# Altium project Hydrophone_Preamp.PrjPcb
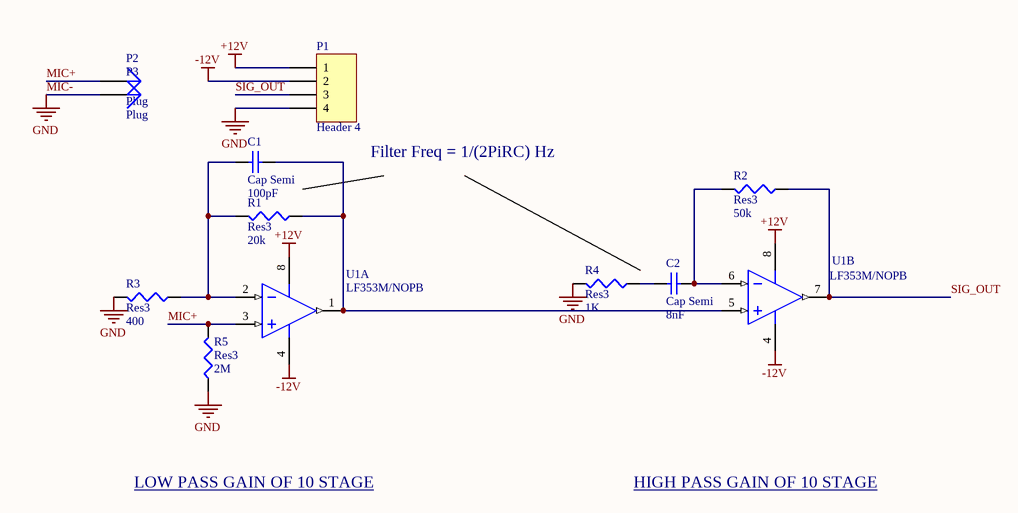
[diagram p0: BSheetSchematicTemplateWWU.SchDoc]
DraftsmanName: [GlobalDraftsmanName]; EngineerName: [GlobalEngineerName]; GlobalDate: [GlobalDate]; GlobalTitle: [GlobalTitle]; RevNumber: [GlobalRevNumber]
1 sheet, 12 parts. Net scope: flat (ports and power ports of the same name join across sheets).
Board file: 2LayerPCBTemplateWWU.PcbDoc

## Sheet BSheetSchematicTemplateWWU.SchDoc: [SheetTitle]
size B; Date: [Date]

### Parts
(Parts that share a designator on the sheet are numbered #1, #2 ... from top to bottom, then left to right.)
C1  Cap Semi  value 100pF  [1608[0603]]
C2  Cap Semi  value 8nF  [1608[0603]]
P1  Header 4  [HDR1X4]
P2  Plug  [PIN1]
P3  Plug  [PIN1]
R1  Res3  value 20k  [J1-0603]
R2  Res3  value 50k  [J1-0603]
R3  Res3  value 400  [J1-0603]
R4  Res3  value 1K  [J1-0603]
R5  Res3  value 2M  [J1-0603]
U1#1  LF353M/NOPB  [D0008A_L]  (part B of 2)
U1#2  LF353M/NOPB  [D0008A_M]  (part A of 2)

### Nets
+12V: P1.1 U1#1.8(V+) U1#2.8(V+)
-12V: P1.2 U1#1.4(V-) U1#2.4(V-)
MIC-: P1.4 P3.1 R3.2 R4.2 R5.1  [also labelled GND]
MIC+: P2.1 R5.2 U1#2.3(INA+)
SIG_OUT: P1.3 R2.1 U1#1.7(OUTB)
NetC1_1: C1.1 R1.2 R3.1 U1#2.2(INA-)
NetC1_2: C1.2 R1.1 U1#1.5(INB+) U1#2.1(OUTA)
NetC2_1: C2.1 R4.1
NetC2_2: C2.2 R2.2 U1#1.6(INB-)

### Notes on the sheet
- Filter Freq = 1/(2PiRC) Hz
- LOW PASS GAIN OF 10 STAGE
- HIGH PASS GAIN OF 10 STAGE

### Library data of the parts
C1 C2 = Cap Semi: Capacitor (Semiconductor SIM Model)
P1 = Header 4: Header, 4-Pin
R1-R5 = Res3: Resistor
U1#1 U1#2 = CMP-0055-00856-3: Wide Bandwidth Dual JFET Input Operational Amplifier, 8-pin Narrow SOIC, Pb-Free; Manufacturer: Texas Instruments; PackageTopMarking: NSZXTT*LF353*M; CompType: Amplifiers; PowerWise: N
